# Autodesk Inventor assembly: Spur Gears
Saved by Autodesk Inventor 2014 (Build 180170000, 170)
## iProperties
Created: 2015-07
Part Number: Spur Gears
Document SubType Name: Assembly
Designer: Brad Factor
Categories: <?xml version="1.0" encoding="UTF-16"?> <MemberInstance><Categories><FamilyTemplate/><ParamToTemplateMap><ParamToTemplate><ParamToTemplate CategoryParameter="//
ClientObjectVersion: 1
Author: Brad Factor
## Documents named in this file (3)
- D:\Projects\Graduate School\Courses\Haptics\HapKit\HapKit Gear Design\Design Accelerator\Spur Gears1.iam
- D:\Projects\Graduate School\Courses\Haptics\HapKit\HapKit Gear Design\Design Accelerator\Spur Gear11.ipt
- D:\Projects\Graduate School\Courses\Haptics\HapKit\HapKit Gear Design\Design Accelerator\Spur Gear21.ipt
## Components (2 placed, 2 different names)
1. Spur Gear1:1 — Rotation:1
2. Spur Gear2:1 — Rotation:1
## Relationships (1: RelateRotation 1)
- Rotation:1 [RelateRotation]: Spur Gear1:1 ↔ Spur Gear2:1
